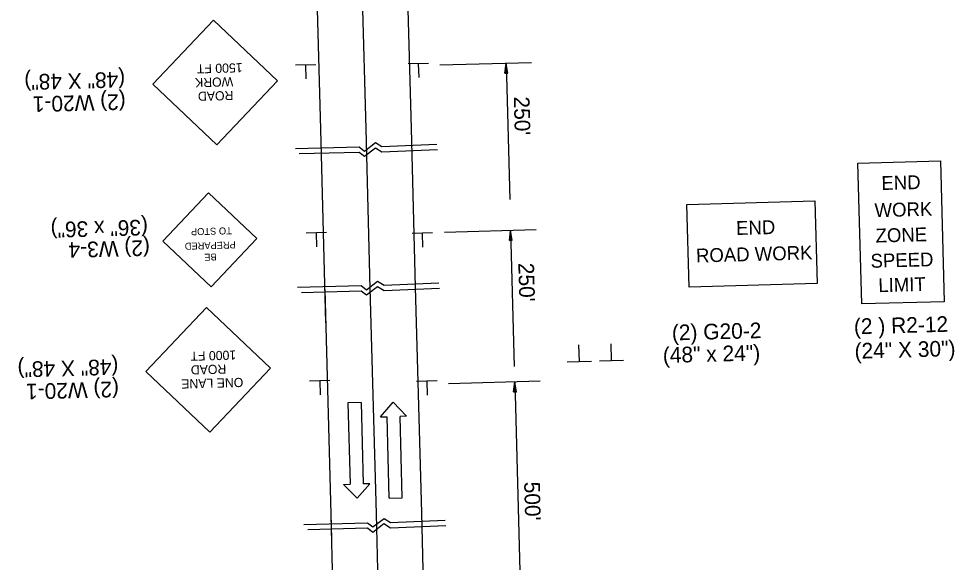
# Model space of a CAD drawing. Extents: x 1929624 to 1932070, y 596315 to 605533.
# Drawn here: x 1930087.8 to 1930454.9, y 598739.7 to 598953.1 of the extents above; entities that cross this region are included whole.
import ezdxf

# ---------------------------------------------------------------- set-up
doc = ezdxf.new("R2010")
doc.units = 0
doc.layers.add('Default', color=7, linetype='Continuous')
doc.layers.add('R_MOT', color=7, linetype='Continuous')

msp = doc.modelspace()

# ---------------------------------------------------------------- linework, layer by layer
at = {"layer": 'Default'}
for p, q in [((1930204.5, 598971.53), (1930206.16, 598909.77)), ((1930222.27, 598972.47), (1930223.95, 598909.9)), ((1930240.04, 598973.42), (1930241.74, 598910.03)), ((1930140.36, 598927.46), (1930164.16, 598952.54)), ((1930164.16, 598952.54), (1930189.27, 598928.77)), ((1930196.34, 598934.99), (1930204.35, 598935.21)), ((1930200.33, 598934.98), (1930200.47, 598929.52)), ((1930240.61, 598935.49), (1930248.62, 598935.7)), ((1930244.6, 598935.48), (1930244.74, 598930.02)), ((1930289.07, 598935.86), (1930253.05, 598934.89)), ((1930278.58, 598931.74), (1930279.05, 598935.59)), ((1930278.68, 598931.74), (1930279.07, 598934.95)), ((1930278.77, 598931.74), (1930279.09, 598934.29)), ((1930279.05, 598935.59), (1930280.49, 598882.21)), ((1930279.73, 598931.77), (1930279.05, 598935.59)), ((1930279.64, 598931.77), (1930279.07, 598934.95)), ((1930279.54, 598931.76), (1930279.09, 598934.29)), ((1930278.58, 598931.74), (1930279.73, 598931.77)), ((1930278.87, 598931.75), (1930279.11, 598933.65)), ((1930278.97, 598931.75), (1930279.12, 598933)), ((1930279.07, 598931.75), (1930279.14, 598932.36)), ((1930279.44, 598931.76), (1930279.11, 598933.65)), ((1930279.34, 598931.76), (1930279.12, 598933)), ((1930279.25, 598931.76), (1930279.14, 598932.36)), ((1930140.36, 598927.46), (1930165.47, 598903.66)), ((1930165.47, 598903.66), (1930189.27, 598928.77)), ((1930206.16, 598909.77), (1930208.2, 598833.72)), ((1930223.95, 598909.9), (1930225.63, 598847.31)), ((1930241.74, 598910.03), (1930243.42, 598847.79)), ((1930144.35, 598865.75), (1930162.28, 598884.73)), ((1930162.28, 598884.73), (1930181.26, 598866.8)), ((1930200.55, 598869.1), (1930208.55, 598869.31)), ((1930204.53, 598869.09), (1930204.68, 598863.63)), ((1930242.16, 598868.92), (1930250.16, 598869.14)), ((1930246.14, 598868.91), (1930246.29, 598863.45)), ((1930290.83, 598870.23), (1930254.81, 598869.26)), ((1930280.34, 598866.11), (1930280.82, 598869.96)), ((1930280.44, 598866.11), (1930280.83, 598869.32)), ((1930280.54, 598866.11), (1930280.85, 598868.66)), ((1930280.82, 598869.96), (1930282.25, 598816.58)), ((1930281.49, 598866.14), (1930280.82, 598869.96)), ((1930281.4, 598866.14), (1930280.83, 598869.32)), ((1930281.3, 598866.13), (1930280.85, 598868.66)), ((1930144.35, 598865.75), (1930163.33, 598847.83)), ((1930163.33, 598847.83), (1930181.26, 598866.8)), ((1930280.34, 598866.11), (1930281.49, 598866.14)), ((1930280.63, 598866.12), (1930280.87, 598868.02)), ((1930280.73, 598866.12), (1930280.88, 598867.37)), ((1930280.83, 598866.12), (1930280.9, 598866.73)), ((1930281.2, 598866.13), (1930280.87, 598868.02)), ((1930281.11, 598866.13), (1930280.88, 598867.37)), ((1930281.01, 598866.13), (1930280.9, 598866.73)), ((1930207.85, 598846.84), (1930210.48, 598748.87)), ((1930225.63, 598847.31), (1930228.01, 598758.73)), ((1930243.42, 598847.79), (1930245.79, 598759.2)), ((1930137.71, 598814.63), (1930161.5, 598839.72)), ((1930161.5, 598839.72), (1930186.61, 598815.95)), ((1930307.82, 598818.61), (1930307.65, 598825.09)), ((1930320.43, 598818.95), (1930320.25, 598825.43)), ((1930312.55, 598818.6), (1930303.06, 598818.35)), ((1930325.15, 598818.94), (1930315.67, 598818.68)), ((1930137.71, 598814.63), (1930162.82, 598790.84)), ((1930162.82, 598790.84), (1930186.61, 598815.95)), ((1930201.89, 598810.99), (1930209.9, 598811.21)), ((1930205.88, 598810.98), (1930206.02, 598805.52)), ((1930243.94, 598810.83), (1930251.94, 598811.04)), ((1930247.92, 598810.82), (1930248.07, 598805.35)), ((1930292.43, 598810.8), (1930256.41, 598809.83)), ((1930281.94, 598806.68), (1930282.41, 598810.53)), ((1930282.03, 598806.68), (1930282.43, 598809.89)), ((1930282.41, 598810.53), (1930285.09, 598710.81)), ((1930283.09, 598806.71), (1930282.41, 598810.53)), ((1930282.99, 598806.71), (1930282.43, 598809.89)), ((1930281.94, 598806.68), (1930283.09, 598806.71)), ((1930282.13, 598806.68), (1930282.45, 598809.23)), ((1930282.23, 598806.68), (1930282.46, 598808.59)), ((1930282.33, 598806.69), (1930282.48, 598807.94)), ((1930282.42, 598806.69), (1930282.5, 598807.3)), ((1930282.9, 598806.7), (1930282.45, 598809.23)), ((1930282.8, 598806.7), (1930282.46, 598808.59)), ((1930282.7, 598806.7), (1930282.48, 598807.94)), ((1930282.6, 598806.7), (1930282.5, 598807.3)), ((1930210.23, 598758.25), (1930214.62, 598594.67)), ((1930228.01, 598758.73), (1930232.4, 598595.15)), ((1930245.79, 598759.2), (1930250.18, 598595.62))]:
    msp.add_line(p, q, dxfattribs=at)
for points in [[(1930251.85, 598903.72), (1930230.34, 598902.82), (1930227.83, 598904.41), (1930223.49, 598901.06), (1930221.4, 598902.71), (1930196.38, 598902.04)], [(1930252.1, 598901.69), (1930230.31, 598900.77), (1930227.8, 598902.37), (1930223.46, 598899.01), (1930221.37, 598900.66), (1930197.87, 598900.03)], [(1930252.67, 598849.26), (1930231.16, 598848.36), (1930228.64, 598849.95), (1930224.3, 598846.6), (1930222.21, 598848.25), (1930197.19, 598847.58)], [(1930252.92, 598847.23), (1930231.13, 598846.31), (1930228.61, 598847.91), (1930224.27, 598844.55), (1930222.18, 598846.2), (1930198.69, 598845.58)], [(1930255.17, 598756.13), (1930233.66, 598755.23), (1930231.14, 598756.82), (1930226.8, 598753.47), (1930224.71, 598755.12), (1930199.69, 598754.45)], [(1930255.42, 598754.1), (1930233.63, 598753.18), (1930231.11, 598754.78), (1930226.77, 598751.42), (1930224.68, 598753.07), (1930201.19, 598752.44)]]:
    msp.add_lwpolyline(points, dxfattribs=at)
for points in [[(1930449.54, 598897.34), (1930451.03, 598842.03), (1930418.59, 598841.16), (1930417.1, 598896.47)], [(1930350.01, 598880.23), (1930400.25, 598881.58), (1930401.12, 598849.15), (1930350.88, 598847.8)]]:
    msp.add_lwpolyline(points, close=True, dxfattribs=at)
at = {"layer": 'R_MOT'}
for p, q in [((1930222.1, 598802.46), (1930216.98, 598802.33)), ((1930216.98, 598802.33), (1930217.84, 598770.39)), ((1930222.1, 598802.46), (1930222.96, 598770.53)), ((1930229.76, 598796.79), (1930234.72, 598802.54)), ((1930234.72, 598802.54), (1930239.99, 598797.07)), ((1930229.76, 598796.79), (1930232.31, 598796.86)), ((1930233.17, 598764.92), (1930232.31, 598796.86)), ((1930239.99, 598797.07), (1930237.43, 598797)), ((1930238.29, 598765.06), (1930237.43, 598797)), ((1930215.28, 598770.32), (1930217.84, 598770.39)), ((1930220.55, 598764.85), (1930215.28, 598770.32)), ((1930225.51, 598770.59), (1930220.55, 598764.85)), ((1930225.51, 598770.59), (1930222.96, 598770.53)), ((1930233.17, 598764.92), (1930238.29, 598765.06))]:
    msp.add_line(p, q, dxfattribs=at)

# ---------------------------------------------------------------- texts
at = {"layer": 'Default'}
for s, height, rotation, p in [('1500 FT', 3.604, 181.5383, (1930175.58, 598935.73)), ('(48" X 48")', 6.1396, 181.5377, (1930129.47, 598932.33)), ('WORK', 3.602, 181.5377, (1930171.9, 598930.22)), ('(2) W20-1', 6.14, 181.5377, (1930129.7, 598923.57)), ('ROAD', 3.603, 181.5381, (1930171.97, 598924.82)), ("250'", 6.14, 271.5377, (1930282.07, 598922.52)), ('END', 5.444, 1.5377, (1930426.41, 598885.88)), ('WORK ', 5.444, 1.5377, (1930423.72, 598875.2)), ('(36" x 36")', 6.1396, 181.5377, (1930138.42, 598874.29)), ('END', 5.444, 1.5377, (1930369.38, 598868.22)), ('TO STOP', 2.737, 181.5383, (1930171.37, 598871.27)), ('ZONE', 5.443, 1.5377, (1930424.13, 598865.25)), ('(2) W3-4', 6.14, 181.5377, (1930139.18, 598866.23)), ('PREPARED', 2.719, 181.638, (1930172.9, 598865.71)), ('BE', 2.72, 181.6381, (1930165.39, 598860.96)), ('ROAD WORK', 5.444, 1.5377, (1930353.65, 598857.41)), ('SPEED', 5.443, 1.5377, (1930422.15, 598855.32)), ("250'", 6.14, 271.5377, (1930283.83, 598857.21)), ('LIMIT', 5.443, 1.5377, (1930425.19, 598845.76)), ('(2 ) R2-12', 6.14, 1.5377, (1930415.63, 598829.25)), ('(2) G20-2', 6.14, 1.5377, (1930344.19, 598826.82)), ('(48" x 24")', 6.1396, 1.5377, (1930340.63, 598817.97)), ('(24" X 30")', 6.1396, 1.5377, (1930415.89, 598819.62)), ('(48" X 48")', 6.1396, 181.5377, (1930126.81, 598819.51)), ('1000 FT', 3.604, 181.5383, (1930173.07, 598822.91)), ('ROAD', 3.602, 181.5377, (1930169.17, 598817.4)), ('(2) W20-1', 6.14, 181.5377, (1930127.05, 598810.75)), ('ONE LANE', 3.603, 181.5381, (1930175.85, 598812.17)), ("500'", 6.14, 271.5377, (1930286.13, 598771.29))]:
    msp.add_text(s, height=height, rotation=rotation, dxfattribs=at).set_placement(p)

doc.saveas('drawing.dxf')
